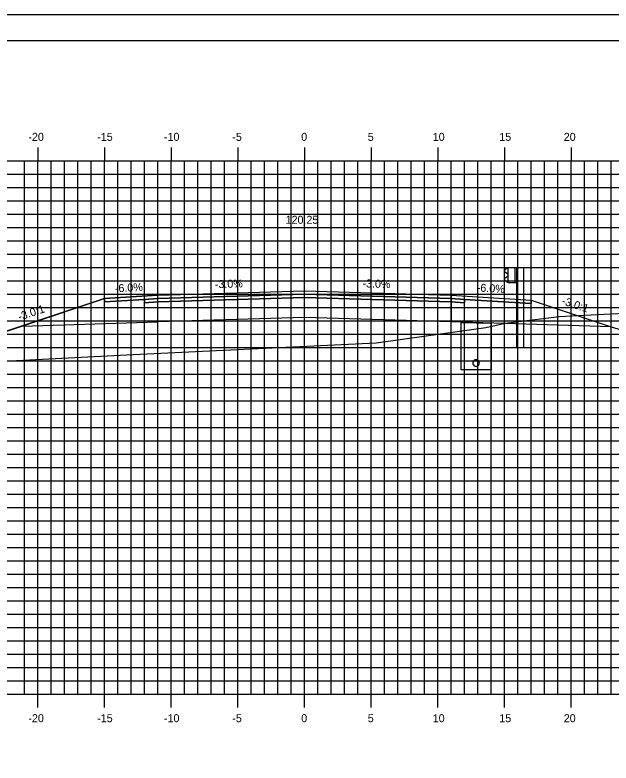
# Model space of a CAD drawing. Extents: x 850598 to 870284, y 366541 to 366651.
# Drawn here: x 851959.7 to 852004.4, y 366595.1 to 366651.2 of the extents above; entities that cross this region are included whole.
import ezdxf

# ---------------------------------------------------------------- set-up
doc = ezdxf.new("R2010")
doc.units = 0
for name, color, linetype in [('ANNOTATION', 7, 'Continuous'), ('BORDER', 7, 'Continuous'), ('D_Drainage_Underdrain', 7, 'Continuous'), ('D_Drainage_Underdrain_06in', 7, 'Continuous'), ('D_Guardrail_Beam_Rt', 7, 'Continuous'), ('D_Roadway_Centerline', 7, 'Continuous'), ('D_Roadway_Centerline_Text', 7, 'Continuous'), ('D_Roadway_Edge_Shoulder', 7, 'Continuous'), ('D_Roadway_Edge_TW', 7, 'Continuous'), ('D_Roadway_Pavement', 7, 'Continuous'), ('D_Roadway_SlopeLines', 7, 'Continuous'), ('D_Roadway_SubGrade', 7, 'Continuous'), ('H_V ANNOTATION', 7, 'Continuous'), ('MAJOR', 7, 'Continuous'), ('MINOR', 7, 'Continuous'), ('PLOT BOUNDARY', 7, 'Continuous'), ('S_Roadway_Centerline', 7, 'Continuous')]:
    doc.layers.add(name, color=color, linetype=linetype)

msp = doc.modelspace()

# ---------------------------------------------------------------- linework, layer by layer
at = {"layer": 'BORDER'}
msp.add_line((852096.436, 366649.225), (851936.436, 366649.225), dxfattribs=at)
at = {"layer": 'D_Drainage_Underdrain'}
msp.add_lwpolyline([(851995.436, 366628.062), (851995.436, 366624.562), (851993.186, 366624.562), (851993.186, 366628.107)], close=True, dxfattribs=at)
at = {"layer": 'D_Drainage_Underdrain_06in'}
msp.add_lwpolyline([(851994.311, 366625.312), (851994.234, 366625.299), (851994.164, 366625.264), (851994.109, 366625.208), (851994.073, 366625.139), (851994.061, 366625.062), (851994.073, 366624.984), (851994.109, 366624.915), (851994.164, 366624.859), (851994.234, 366624.824), (851994.311, 366624.812), (851994.388, 366624.824), (851994.458, 366624.859), (851994.513, 366624.915), (851994.549, 366624.984), (851994.561, 366625.062), (851994.549, 366625.139), (851994.513, 366625.208), (851994.458, 366625.264), (851994.388, 366625.299)], close=True, dxfattribs=at)
at = {"layer": 'D_Guardrail_Beam_Rt'}
for p, q in [((851996.707, 366632.237), (851997.395, 366632.237)), ((851996.707, 366631.071), (851996.707, 366632.237)), ((851997.228, 366632.237), (851997.228, 366631.071)), ((851997.332, 366632.237), (851997.332, 366631.071)), ((851997.395, 366632.237), (851997.865, 366632.237)), ((851997.395, 366632.237), (851997.395, 366631.071)), ((851997.865, 366632.237), (851997.865, 366626.237)), ((851996.617, 366632.143), (851996.474, 366632.043)), ((851996.474, 366631.9), (851996.669, 366631.764)), ((851996.707, 366632.163), (851996.634, 366632.15)), ((851996.703, 366631.7), (851996.703, 366631.608)), ((851996.669, 366631.544), (851996.474, 366631.408)), ((851996.474, 366631.265), (851996.617, 366631.165)), ((851996.634, 366631.158), (851996.707, 366631.145)), ((851997.395, 366631.071), (851996.707, 366631.071)), ((851997.374, 366626.237), (851997.374, 366631.071)), ((851997.374, 366626.237), (851997.865, 366626.237))]:
    msp.add_line(p, q, dxfattribs=at)
for centre, major_axis, start_param, end_param in [((851996.524, 366631.972), (-0.0877, 0), 5.323254, 7.243116), ((851996.641, 366632.109), (-0.0417, 0), 4.886922, 5.323254), ((851996.624, 366631.7), (0.0789, 0), 0, 0.959931), ((851996.524, 366631.336), (-0.0877, 0), 5.323254, 7.243116), ((851996.641, 366631.199), (-0.0417, 0), 0.959931, 1.396263), ((851996.624, 366631.608), (0.0789, 0), 5.323254, 6.283185)]:
    msp.add_ellipse(centre, major_axis=major_axis, ratio=0.995501, start_param=start_param, end_param=end_param, dxfattribs=at)
at = {"layer": 'D_Roadway_Centerline'}
msp.add_lwpolyline([(851951.16, 366624.812), (851956.436, 366626.571), (851960.238, 366627.838), (851966.436, 366629.904), (851970.436, 366630.144), (851981.436, 366630.474), (851992.436, 366630.144), (851996.436, 366629.904), (851998.436, 366629.784), (852004.436, 366627.784), (852036.099, 366618.225), (852046.112, 366615.203), (852055.974, 366612.225), (852059.974, 366612.225)], dxfattribs=at)
at = {"layer": 'D_Roadway_Edge_Shoulder'}
for points in [[(851970.436, 366630.144), (851966.436, 366629.904), (851966.436, 366629.654), (851969.436, 366629.834), (851970.436, 366629.894)], [(851992.436, 366630.144), (851996.436, 366629.904), (851996.436, 366629.904), (851998.436, 366629.784), (851998.436, 366629.534), (851993.436, 366629.834), (851992.436, 366629.894)]]:
    msp.add_lwpolyline(points, close=True, dxfattribs=at)
at = {"layer": 'D_Roadway_Edge_TW'}
msp.add_lwpolyline([(851970.436, 366629.894), (851970.436, 366630.144), (851981.436, 366630.474), (851992.436, 366630.144), (851992.436, 366629.894), (851981.436, 366630.224)], close=True, dxfattribs=at)
at = {"layer": 'D_Roadway_Pavement'}
for points in [[(851970.436, 366629.644), (851970.436, 366629.894), (851981.436, 366630.224), (851992.436, 366629.894), (851992.436, 366629.644), (851981.436, 366629.974)], [(851970.436, 366629.894), (851969.436, 366629.834), (851969.436, 366629.584), (851970.436, 366629.644)], [(851992.436, 366629.894), (851993.436, 366629.834), (851993.436, 366629.584), (851992.436, 366629.644)]]:
    msp.add_lwpolyline(points, close=True, dxfattribs=at)
at = {"layer": 'D_Roadway_SlopeLines'}
msp.add_lwpolyline([(851970.436, 366630.144), (851966.436, 366629.904), (851956.436, 366626.571)], dxfattribs=at)
at = {"layer": 'D_Roadway_SubGrade'}
for points in [[(851970.436, 366629.644), (851969.436, 366629.584), (851969.436, 366629.834), (851966.436, 366629.654), (851966.436, 366629.904), (851960.238, 366627.838), (851970.436, 366628.144)], [(851970.436, 366628.144), (851970.436, 366629.644), (851981.436, 366629.974), (851992.436, 366629.644), (851992.436, 366628.144), (851981.436, 366628.474)], [(851992.436, 366629.644), (851993.436, 366629.584), (851993.436, 366629.834), (851998.436, 366629.534), (851998.436, 366629.784), (852004.436, 366627.784), (851992.436, 366628.144)]]:
    msp.add_lwpolyline(points, close=True, dxfattribs=at)
at = {"layer": 'MAJOR'}
for p, q in [((851961.436, 366641.227), (851961.436, 366640.225)), ((851961.436, 366641.227), (851961.436, 366640.225)), ((851966.436, 366641.227), (851966.436, 366640.225)), ((851966.436, 366641.227), (851966.436, 366640.225)), ((851971.436, 366641.227), (851971.436, 366640.225)), ((851971.436, 366641.227), (851971.436, 366640.225)), ((851976.436, 366641.227), (851976.436, 366640.225)), ((851976.436, 366641.227), (851976.436, 366640.225)), ((851981.436, 366641.227), (851981.436, 366640.225)), ((851981.436, 366641.227), (851981.436, 366640.225)), ((851986.436, 366641.227), (851986.436, 366640.225)), ((851986.436, 366641.227), (851986.436, 366640.225)), ((851991.436, 366641.227), (851991.436, 366640.225)), ((851991.436, 366641.227), (851991.436, 366640.225)), ((851996.436, 366641.227), (851996.436, 366640.225)), ((851996.436, 366641.227), (851996.436, 366640.225)), ((852001.436, 366641.227), (852001.436, 366640.225)), ((852001.436, 366641.227), (852001.436, 366640.225)), ((851941.436, 366640.225), (852081.436, 366640.225)), ((851941.436, 366640.225), (852081.436, 366640.225)), ((851941.436, 366640.225), (852081.436, 366640.225)), ((851941.436, 366640.225), (852081.436, 366640.225)), ((851961.436, 366600.225), (851961.436, 366640.225)), ((851961.436, 366600.225), (851961.436, 366640.225)), ((851966.436, 366600.225), (851966.436, 366640.225)), ((851966.436, 366600.225), (851966.436, 366640.225)), ((851971.436, 366600.225), (851971.436, 366640.225)), ((851971.436, 366600.225), (851971.436, 366640.225)), ((851976.436, 366600.225), (851976.436, 366640.225)), ((851976.436, 366600.225), (851976.436, 366640.225)), ((851981.436, 366600.225), (851981.436, 366640.225)), ((851981.436, 366600.225), (851981.436, 366640.225)), ((851986.436, 366600.225), (851986.436, 366640.225)), ((851986.436, 366600.225), (851986.436, 366640.225)), ((851991.436, 366600.225), (851991.436, 366640.225)), ((851991.436, 366600.225), (851991.436, 366640.225)), ((851996.436, 366600.225), (851996.436, 366640.225)), ((851996.436, 366600.225), (851996.436, 366640.225)), ((852001.436, 366600.225), (852001.436, 366640.225)), ((852001.436, 366600.225), (852001.436, 366640.225)), ((851941.436, 366635.225), (852081.436, 366635.225)), ((851941.436, 366635.225), (852081.436, 366635.225)), ((851941.436, 366630.225), (852081.436, 366630.225)), ((851941.436, 366630.225), (852081.436, 366630.225)), ((851941.436, 366625.225), (852081.436, 366625.225)), ((851941.436, 366625.225), (852081.436, 366625.225)), ((851941.436, 366620.225), (852081.436, 366620.225)), ((851941.436, 366620.225), (852081.436, 366620.225)), ((851941.436, 366615.225), (852081.436, 366615.225)), ((851941.436, 366615.225), (852081.436, 366615.225)), ((851941.436, 366610.225), (852081.436, 366610.225)), ((851941.436, 366610.225), (852081.436, 366610.225)), ((851941.436, 366605.225), (852081.436, 366605.225)), ((851941.436, 366605.225), (852081.436, 366605.225)), ((851941.436, 366600.225), (852081.436, 366600.225)), ((851941.436, 366600.225), (852081.436, 366600.225)), ((851941.436, 366600.225), (852081.436, 366600.225)), ((851941.436, 366600.225), (852081.436, 366600.225)), ((851961.436, 366599.223), (851961.436, 366600.225)), ((851961.436, 366599.223), (851961.436, 366600.225)), ((851966.436, 366599.223), (851966.436, 366600.225)), ((851966.436, 366599.223), (851966.436, 366600.225)), ((851971.436, 366599.223), (851971.436, 366600.225)), ((851971.436, 366599.223), (851971.436, 366600.225)), ((851976.436, 366599.223), (851976.436, 366600.225)), ((851976.436, 366599.223), (851976.436, 366600.225)), ((851981.436, 366599.223), (851981.436, 366600.225)), ((851981.436, 366599.223), (851981.436, 366600.225)), ((851986.436, 366599.223), (851986.436, 366600.225)), ((851986.436, 366599.223), (851986.436, 366600.225)), ((851991.436, 366599.223), (851991.436, 366600.225)), ((851991.436, 366599.223), (851991.436, 366600.225)), ((851996.436, 366599.223), (851996.436, 366600.225)), ((851996.436, 366599.223), (851996.436, 366600.225)), ((852001.436, 366599.223), (852001.436, 366600.225)), ((852001.436, 366599.223), (852001.436, 366600.225))]:
    msp.add_line(p, q, dxfattribs=at)
at = {"layer": 'MINOR'}
for p, q in [((851960.436, 366600.225), (851960.436, 366640.225)), ((851960.436, 366600.225), (851960.436, 366640.225)), ((851962.436, 366600.225), (851962.436, 366640.225)), ((851962.436, 366600.225), (851962.436, 366640.225)), ((851963.436, 366600.225), (851963.436, 366640.225)), ((851963.436, 366600.225), (851963.436, 366640.225)), ((851964.436, 366600.225), (851964.436, 366640.225)), ((851964.436, 366600.225), (851964.436, 366640.225)), ((851965.436, 366600.225), (851965.436, 366640.225)), ((851965.436, 366600.225), (851965.436, 366640.225)), ((851967.436, 366600.225), (851967.436, 366640.225)), ((851967.436, 366600.225), (851967.436, 366640.225)), ((851968.436, 366600.225), (851968.436, 366640.225)), ((851968.436, 366600.225), (851968.436, 366640.225)), ((851969.436, 366600.225), (851969.436, 366640.225)), ((851969.436, 366600.225), (851969.436, 366640.225)), ((851970.436, 366600.225), (851970.436, 366640.225)), ((851970.436, 366600.225), (851970.436, 366640.225)), ((851972.436, 366600.225), (851972.436, 366640.225)), ((851972.436, 366600.225), (851972.436, 366640.225)), ((851973.436, 366600.225), (851973.436, 366640.225)), ((851973.436, 366600.225), (851973.436, 366640.225)), ((851974.436, 366600.225), (851974.436, 366640.225)), ((851974.436, 366600.225), (851974.436, 366640.225)), ((851975.436, 366600.225), (851975.436, 366640.225)), ((851975.436, 366600.225), (851975.436, 366640.225)), ((851977.436, 366600.225), (851977.436, 366640.225)), ((851977.436, 366600.225), (851977.436, 366640.225)), ((851978.436, 366600.225), (851978.436, 366640.225)), ((851978.436, 366600.225), (851978.436, 366640.225)), ((851979.436, 366600.225), (851979.436, 366640.225)), ((851979.436, 366600.225), (851979.436, 366640.225)), ((851980.436, 366600.225), (851980.436, 366640.225)), ((851980.436, 366600.225), (851980.436, 366640.225)), ((851982.436, 366600.225), (851982.436, 366640.225)), ((851982.436, 366600.225), (851982.436, 366640.225)), ((851983.436, 366600.225), (851983.436, 366640.225)), ((851983.436, 366600.225), (851983.436, 366640.225)), ((851984.436, 366600.225), (851984.436, 366640.225)), ((851984.436, 366600.225), (851984.436, 366640.225)), ((851985.436, 366600.225), (851985.436, 366640.225)), ((851985.436, 366600.225), (851985.436, 366640.225)), ((851987.436, 366600.225), (851987.436, 366640.225)), ((851987.436, 366600.225), (851987.436, 366640.225)), ((851988.436, 366600.225), (851988.436, 366640.225)), ((851988.436, 366600.225), (851988.436, 366640.225)), ((851989.436, 366600.225), (851989.436, 366640.225)), ((851989.436, 366600.225), (851989.436, 366640.225)), ((851990.436, 366600.225), (851990.436, 366640.225)), ((851990.436, 366600.225), (851990.436, 366640.225)), ((851992.436, 366600.225), (851992.436, 366640.225)), ((851992.436, 366600.225), (851992.436, 366640.225)), ((851993.436, 366600.225), (851993.436, 366640.225)), ((851993.436, 366600.225), (851993.436, 366640.225)), ((851994.436, 366600.225), (851994.436, 366640.225)), ((851994.436, 366600.225), (851994.436, 366640.225)), ((851995.436, 366600.225), (851995.436, 366640.225)), ((851995.436, 366600.225), (851995.436, 366640.225)), ((851997.436, 366600.225), (851997.436, 366640.225)), ((851997.436, 366600.225), (851997.436, 366640.225)), ((851998.436, 366600.225), (851998.436, 366640.225)), ((851998.436, 366600.225), (851998.436, 366640.225)), ((851999.436, 366600.225), (851999.436, 366640.225)), ((851999.436, 366600.225), (851999.436, 366640.225)), ((852000.436, 366600.225), (852000.436, 366640.225)), ((852000.436, 366600.225), (852000.436, 366640.225)), ((852002.436, 366600.225), (852002.436, 366640.225)), ((852002.436, 366600.225), (852002.436, 366640.225)), ((852003.436, 366600.225), (852003.436, 366640.225)), ((852003.436, 366600.225), (852003.436, 366640.225)), ((852004.436, 366600.225), (852004.436, 366640.225)), ((852004.436, 366600.225), (852004.436, 366640.225)), ((851941.436, 366639.225), (852081.436, 366639.225)), ((851941.436, 366639.225), (852081.436, 366639.225)), ((851941.436, 366638.225), (852081.436, 366638.225)), ((851941.436, 366638.225), (852081.436, 366638.225)), ((851941.436, 366637.225), (852081.436, 366637.225)), ((851941.436, 366637.225), (852081.436, 366637.225)), ((851941.436, 366636.225), (852081.436, 366636.225)), ((851941.436, 366636.225), (852081.436, 366636.225)), ((851941.436, 366634.225), (852081.436, 366634.225)), ((851941.436, 366634.225), (852081.436, 366634.225)), ((851941.436, 366633.225), (852081.436, 366633.225)), ((851941.436, 366633.225), (852081.436, 366633.225)), ((851941.436, 366632.225), (852081.436, 366632.225)), ((851941.436, 366632.225), (852081.436, 366632.225)), ((851941.436, 366631.225), (852081.436, 366631.225)), ((851941.436, 366631.225), (852081.436, 366631.225)), ((851941.436, 366629.225), (852081.436, 366629.225)), ((851941.436, 366629.225), (852081.436, 366629.225)), ((851941.436, 366628.225), (852081.436, 366628.225)), ((851941.436, 366628.225), (852081.436, 366628.225)), ((851941.436, 366627.225), (852081.436, 366627.225)), ((851941.436, 366627.225), (852081.436, 366627.225)), ((851941.436, 366626.225), (852081.436, 366626.225)), ((851941.436, 366626.225), (852081.436, 366626.225)), ((851941.436, 366624.225), (852081.436, 366624.225)), ((851941.436, 366624.225), (852081.436, 366624.225)), ((851941.436, 366623.225), (852081.436, 366623.225)), ((851941.436, 366623.225), (852081.436, 366623.225)), ((851941.436, 366622.225), (852081.436, 366622.225)), ((851941.436, 366622.225), (852081.436, 366622.225)), ((851941.436, 366621.225), (852081.436, 366621.225)), ((851941.436, 366621.225), (852081.436, 366621.225)), ((851941.436, 366619.225), (852081.436, 366619.225)), ((851941.436, 366619.225), (852081.436, 366619.225)), ((851941.436, 366618.225), (852081.436, 366618.225)), ((851941.436, 366618.225), (852081.436, 366618.225)), ((851941.436, 366617.225), (852081.436, 366617.225)), ((851941.436, 366617.225), (852081.436, 366617.225)), ((851941.436, 366616.225), (852081.436, 366616.225)), ((851941.436, 366616.225), (852081.436, 366616.225)), ((851941.436, 366614.225), (852081.436, 366614.225)), ((851941.436, 366614.225), (852081.436, 366614.225)), ((851941.436, 366613.225), (852081.436, 366613.225)), ((851941.436, 366613.225), (852081.436, 366613.225)), ((851941.436, 366612.225), (852081.436, 366612.225)), ((851941.436, 366612.225), (852081.436, 366612.225)), ((851941.436, 366611.225), (852081.436, 366611.225)), ((851941.436, 366611.225), (852081.436, 366611.225)), ((851941.436, 366609.225), (852081.436, 366609.225)), ((851941.436, 366609.225), (852081.436, 366609.225)), ((851941.436, 366608.225), (852081.436, 366608.225)), ((851941.436, 366608.225), (852081.436, 366608.225)), ((851941.436, 366607.225), (852081.436, 366607.225)), ((851941.436, 366607.225), (852081.436, 366607.225)), ((851941.436, 366606.225), (852081.436, 366606.225)), ((851941.436, 366606.225), (852081.436, 366606.225)), ((851941.436, 366604.225), (852081.436, 366604.225)), ((851941.436, 366604.225), (852081.436, 366604.225)), ((851941.436, 366603.225), (852081.436, 366603.225)), ((851941.436, 366603.225), (852081.436, 366603.225)), ((851941.436, 366602.225), (852081.436, 366602.225)), ((851941.436, 366602.225), (852081.436, 366602.225)), ((851941.436, 366601.225), (852081.436, 366601.225)), ((851941.436, 366601.225), (852081.436, 366601.225))]:
    msp.add_line(p, q, dxfattribs=at)
at = {"layer": 'PLOT BOUNDARY'}
msp.add_lwpolyline([(851928.343, 366541.166), (852098.343, 366541.166), (852098.343, 366651.166), (851928.343, 366651.166)], close=True, dxfattribs=at)
at = {"layer": 'S_Roadway_Centerline'}
msp.add_lwpolyline([(851941.436, 366624.619), (851946.198, 366624.56), (851968.596, 366625.699), (851986.828, 366626.579), (851995.049, 366627.725), (851996.482, 366628.04), (851997.32, 366628.156), (852000.545, 366628.561), (852002.937, 366628.672), (852015.281, 366629.309), (852017.599, 366629.322), (852031.301, 366629.429), (852032.808, 366628.857), (852036.025, 366627.589), (852038.86, 366626.482), (852043.581, 366622.758), (852051.848, 366616.471), (852055.701, 366614.478), (852069.779, 366607.058), (852081.436, 366606.213)], dxfattribs=at)

# ---------------------------------------------------------------- texts
at = {"layer": 'ANNOTATION'}
for s, rotation, p in [('-3.0%', 1.7184, (851974.724, 366630.673)), ('-3.0%', 358.2816, (851985.784, 366630.744)), ('-6.0%', 3.4336, (851967.233, 366630.354)), ('-6.0%', 356.5664, (851994.353, 366630.431)), ('-3.0:1', 341.5651, (852000.69, 366629.487)), ('-3.0:1', 18.4348, (851960.058, 366628.232))]:
    msp.add_text(s, height=0.6, rotation=rotation, dxfattribs=at).set_placement(p)
at = {"layer": 'D_Roadway_Centerline'}
for s, p in [('C', (851981.431, 366630.474)), ('C', (851981.431, 366630.474)), ('L', (851981.436, 366630.467)), ('L', (851981.436, 366630.467))]:
    msp.add_text(s, height=0.0146, dxfattribs=at).set_placement(p)
at = {"layer": 'D_Roadway_Centerline_Text'}
msp.add_text('120.25', height=0.6, dxfattribs=at).set_placement((851980.026, 366635.506))
at = {"layer": 'H_V ANNOTATION'}
for s, p in [('-20', (851960.73, 366641.725)), ('-10', (851970.901, 366641.725)), ('0', (851981.195, 366641.725)), ('10', (851991.062, 366641.725)), ('20', (852000.89, 366641.725)), ('-15', (851965.893, 366641.725)), ('-5', (851976.027, 366641.725)), ('5', (851986.187, 366641.725)), ('15', (851996.054, 366641.725)), ('-20', (851960.73, 366598.125)), ('-15', (851965.893, 366598.125)), ('-10', (851970.901, 366598.125)), ('-5', (851976.027, 366598.125)), ('0', (851981.195, 366598.125)), ('5', (851986.187, 366598.125)), ('10', (851991.062, 366598.125)), ('15', (851996.054, 366598.125)), ('20', (852000.89, 366598.125))]:
    msp.add_text(s, height=0.6, dxfattribs=at).set_placement(p)

doc.saveas('drawing.dxf')
